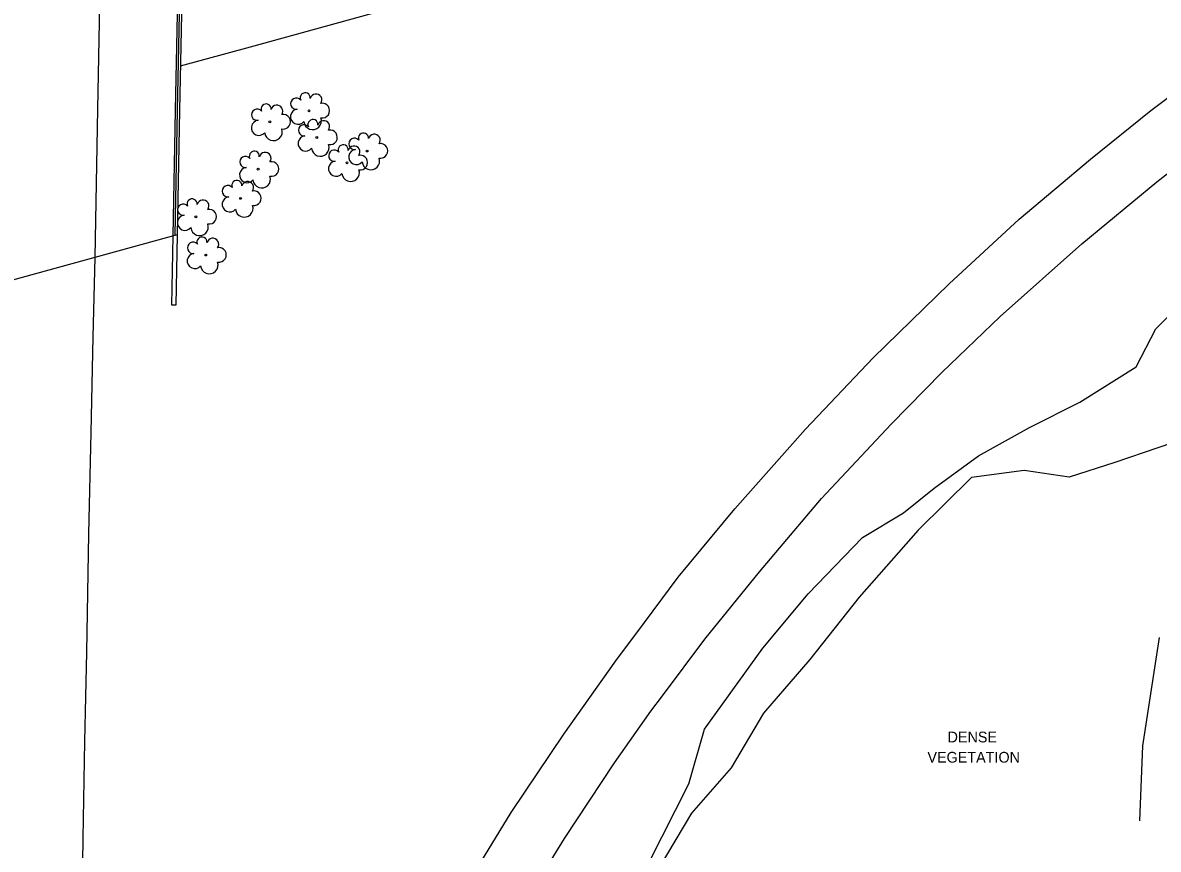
# Model space of a CAD drawing. Extents: x 2129547 to 2134906, y 657330 to 659734.
# Drawn here: x 2132484.8 to 2132780.8, y 658244 to 658459.3 of the extents above; entities that cross this region are included whole.
import ezdxf

# ---------------------------------------------------------------- set-up
doc = ezdxf.new("R2010")
doc.units = 0
for name, color, linetype in [('BR_X_SV_Deck_Top', 7, 'Continuous'), ('DT_X_Void', 7, 'Continuous'), ('PM_X_Edge_Line', 7, 'Continuous'), ('PM_X_Lane_Line', 7, 'Continuous'), ('RD_X_Fence', 7, 'Continuous'), ('RD_X_Misc_Items', 7, 'Continuous'), ('RD_X_Wall', 7, 'Continuous'), ('VG_X_Cells', 7, 'Continuous'), ('VG_X_Text', 7, 'Continuous'), ('VG_X_Tree_Line_Lt', 7, 'Continuous')]:
    doc.layers.add(name, color=color, linetype=linetype)

# ---------------------------------------------------------------- blocks, each defined once
blk = doc.blocks.new('TREE')
at = {"layer": 'VG_X_Cells'}
blk.add_circle((0, 0), 0.00305, dxfattribs=at)
for centre, radius, start, end in [((-0.042, 0.0237), 0.0187, 39.0625, 279.5412), ((-0.0125, 0.0428), 0.0167, 354.0047, 205.9741), ((0.0232, 0.0359), 0.0197, 323.83, 165.0376), ((-0.0362, -0.0197), 0.0251, 96.1722, 320.5737), ((0.0439, 0.0005), 0.0243, 259.1453, 101.4596), ((0.012, -0.0331), 0.029, 184.9476, 19.4572)]:
    blk.add_arc(centre, radius, start, end, dxfattribs=at)

msp = doc.modelspace()

# ---------------------------------------------------------------- linework, layer by layer
at = {"layer": 'BR_X_SV_Deck_Top'}
msp.add_lwpolyline([(2132530.48, 658676.28), (2132529.61, 658630.47), (2132528.8, 658593.03), (2132527.85, 658548.59), (2132526.78, 658491.02), (2132525.63, 658436.44), (2132525.06, 658404.09), (2132445.09, 658382.12), (2132445.85, 658417.49), (2132446.61, 658459.94), (2132448.03, 658522.99), (2132448.8, 658571.92), (2132449.56, 658612.57), (2132450.41, 658654.1)], close=True, dxfattribs=at)
at = {"layer": 'DT_X_Void'}
msp.add_lwpolyline([(2132530.48, 658676.28), (2132529.61, 658630.47), (2132528.8, 658593.03), (2132527.85, 658548.59), (2132526.78, 658491.02), (2132525.63, 658436.44), (2132525.06, 658404.09), (2132445.09, 658382.12), (2132445.85, 658417.49), (2132446.61, 658459.94), (2132448.03, 658522.99), (2132448.8, 658571.92), (2132449.56, 658612.57), (2132450.41, 658654.1)], close=True, dxfattribs=at)
at = {"layer": 'PM_X_Edge_Line'}
for points in [[(2133158.51, 658623.08), (2133137.32, 658617.18), (2133107.75, 658608.87), (2133069.12, 658598.17), (2133036.14, 658589.08), (2133001.62, 658579.74), (2132965.01, 658569.7), (2132930.32, 658560.06), (2132893.98, 658550.04), (2132857.01, 658539.9), (2132824.05, 658530.67), (2132784.28, 658519.67), (2132746.13, 658509.23), (2132706.06, 658498.15), (2132669.95, 658488.27), (2132635.09, 658478.56), (2132605.57, 658470.07), (2132586.69, 658464.73), (2132544.05, 658452.96), (2132525.87, 658448)], [(2132599.45, 658232.83), (2132612.14, 658253.6), (2132625.83, 658273.97), (2132639.39, 658293.09), (2132646.86, 658303.1), (2132655.62, 658314.91), (2132670.46, 658332.72), (2132688.85, 658353.43), (2132706.51, 658372.04), (2132726.3, 658391.35), (2132744.55, 658408.18), (2132763.16, 658423.8), (2132778.88, 658436.51), (2132797.28, 658450.31)], [(2132611.72, 658223.57), (2132626.05, 658246.77), (2132639.07, 658266.48), (2132648.54, 658279.95), (2132651.59, 658283.96), (2132662.57, 658298.78), (2132676.88, 658316.26), (2132693, 658335.38), (2132711.19, 658354.73), (2132724.39, 658368.2), (2132739.57, 658382.8), (2132760.87, 658401.73), (2132780.42, 658417.85), (2132794.53, 658428.85)]]:
    msp.add_lwpolyline(points, dxfattribs=at)
at = {"layer": 'PM_X_Lane_Line'}
for points in [[(2132503.65, 658398.19), (2132504.4, 658436.86), (2132505.45, 658491.44), (2132506.56, 658549.01), (2132507.4, 658593.49), (2132507.4, 658593.5), (2132508.1, 658630.95), (2132508.83, 658670.27)], [(2132503.6, 658398.19), (2132503.09, 658377.47), (2132502.58, 658352.54), (2132501.97, 658326.21), (2132501.38, 658295.33), (2132500.9, 658272.06), (2132500.5, 658246.92), (2132500.04, 658215.33), (2132499.74, 658182.46), (2132499.63, 658155.29), (2132499.86, 658127.46), (2132500.32, 658095.82), (2132500.8, 658066.58), (2132501.04, 658044.97), (2132501.15, 658013.81), (2132500.9, 657985.86), (2132500.74, 657955.54), (2132499.92, 657926.93), (2132499.27, 657899.62), (2132498.78, 657869.82), (2132498.51, 657843.52), (2132498.18, 657822.42), (2132497.65, 657796.23)]]:
    msp.add_lwpolyline(points, dxfattribs=at)
at = {"layer": 'RD_X_Fence'}
msp.add_lwpolyline([(2132524.56, 658403.95), (2132525.13, 658436.45), (2132526.28, 658491.03), (2132527.35, 658548.6), (2132528.3, 658593.04), (2132529.11, 658630.48), (2132529.98, 658676.14)], dxfattribs=at)
at = {"layer": 'RD_X_Misc_Items'}
msp.add_lwpolyline([(2132791.91, 658352.39), (2132769.5, 658344.74), (2132757.55, 658340.95), (2132745.83, 658342.7), (2132732.13, 658340.83), (2132718.2, 658327.11), (2132702.81, 658309.71), (2132689.99, 658293.42), (2132677.93, 658279.5), (2132669.49, 658265.25), (2132659.14, 658253.41), (2132650.69, 658239.25)], dxfattribs=at)
at = {"layer": 'RD_X_Wall'}
msp.add_lwpolyline([(2132525.06, 658404.09), (2132524.67, 658385.74), (2132523.67, 658385.77), (2132524.05, 658403.81), (2132524.63, 658436.46), (2132525.78, 658491.04), (2132526.85, 658548.61), (2132527.8, 658593.05), (2132528.61, 658630.49), (2132529.47, 658676), (2132529.99, 658694.83), (2132530.99, 658694.8), (2132530.48, 658676.28)], dxfattribs=at)
at = {"layer": 'VG_X_Tree_Line_Lt'}
for points in [[(2132647.98, 658240.45), (2132658.44, 658261.04), (2132662.56, 658275.29), (2132677.73, 658296.37), (2132689.54, 658310.59), (2132703.67, 658325.25), (2132714.35, 658331.61), (2132722.42, 658338.12), (2132733.93, 658346.49), (2132747.25, 658353.91), (2132760.39, 658360.47), (2132775.05, 658369.71), (2132780.17, 658379.55), (2132785.31, 658384.71)], [(2132781.08, 658299.14), (2132776.72, 658270.92), (2132775.88, 658251.42)]]:
    msp.add_lwpolyline(points, dxfattribs=at)

# ---------------------------------------------------------------- block references
at = {"layer": 'VG_X_Cells', "xscale": 78.74000000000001, "yscale": 78.74000000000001}
for p in [(2132559.42, 658436.4), (2132549.22, 658433.5), (2132561.43, 658429.44), (2132574.6, 658425.91), (2132569.33, 658422.86), (2132546.15, 658421.19), (2132541.6, 658413.58), (2132529.95, 658408.77), (2132532.5, 658398.82)]:
    msp.add_blockref('TREE', p, dxfattribs=at)

# ---------------------------------------------------------------- texts
at = {"layer": 'VG_X_Text'}
for s, p in [('DENSE', (2132725.88, 658271.85)), ('VEGETATION', (2132720.63, 658266.57))]:
    msp.add_text(s, height=2.8, dxfattribs=at).set_placement(p)

doc.saveas('drawing.dxf')
